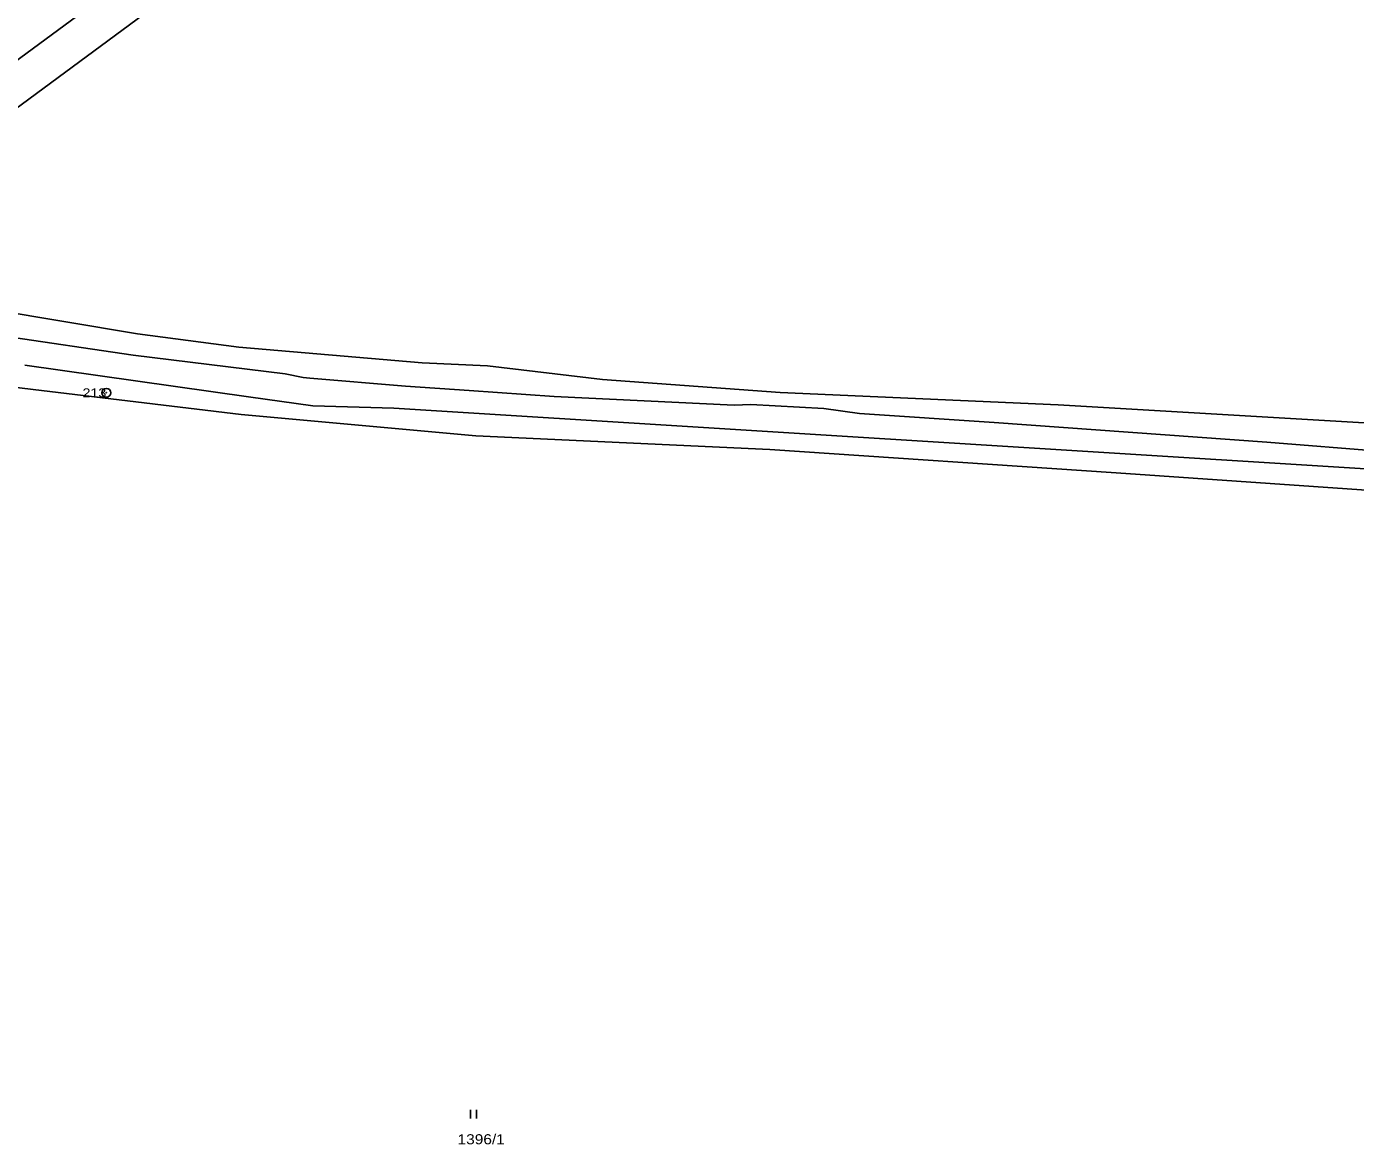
# Model space of a CAD drawing. Extents: x -872229 to -869198, y -1075981 to -1074329.
# Drawn here: x -870489.1 to -870264.6, y -1075125.3 to -1074936.4 of the extents above; entities that cross this region are included whole.
import ezdxf
from ezdxf.enums import TextEntityAlignment as Align

# ---------------------------------------------------------------- set-up
doc = ezdxf.new("R2010")
doc.units = 0
doc.header["$LTSCALE"] = 0.68
for name, color, linetype, lineweight in [('1', 7, 'Continuous', 25), ('3', 7, 'Continuous', 25), ('8', 7, 'Continuous', 25)]:
    doc.layers.add(name, color=color, linetype=linetype, lineweight=lineweight)
doc.layers.add('2', color=7, linetype='Continuous')

msp = doc.modelspace()

# ---------------------------------------------------------------- linework, layer by layer
at = {"layer": '1'}
for points in [[(-870352.08, -1074839.16), (-870370.51, -1074852.86), (-870398.03, -1074874.22), (-870412.45, -1074885.65), (-870420.69, -1074894.67), (-870447.23, -1074917.28), (-870451.03, -1074920.77), (-870491.11, -1074950.4), (-870524.35, -1074974.36)], [(-870388.3, -1074858.96), (-870401.56, -1074868.78), (-870415.98, -1074880.21), (-870424.22, -1074889.23), (-870450.76, -1074911.84), (-870454.56, -1074915.33), (-870494.64, -1074944.96)], [(-870115.36, -1074981.96), (-870117.37, -1074995.15), (-870140.21, -1074996.52), (-870172.56, -1075001.14), (-870203.84, -1075002.96), (-870227.79, -1075005.61), (-870254.49, -1075003.89), (-870314.81, -1075000.31), (-870361.75, -1074998.26), (-870391.78, -1074996.03), (-870411.2, -1074993.72), (-870422.25, -1074993.21), (-870453.27, -1074990.57), (-870470.34, -1074988.35), (-870494.98, -1074984.19), (-870516.43, -1074977.89), (-870524.35, -1074974.36)], [(-870610.36, -1075011.6), (-870588.87, -1075001.44), (-870569.21, -1074993.58), (-870546.64, -1074988.8), (-870536.79, -1074988.15), (-870527.6, -1074989.88), (-870515.91, -1074994.03), (-870492.69, -1074997.19), (-870452.83, -1075001.97), (-870413.18, -1075005.54), (-870363.54, -1075007.87), (-870304.97, -1075011.83), (-870245.64, -1075015.91), (-870217.62, -1075016.65), (-870207.57, -1075016.13)], [(-870240.2, -1075009.79), (-870279.52, -1075006.66), (-870325.61, -1075003.29), (-870348.35, -1075001.79), (-870354.38, -1075000.94), (-870366.75, -1075000.26), (-870369.54, -1075000.39), (-870399.94, -1074998.89), (-870414.32, -1074997.88), (-870425.07, -1074997.15), (-870441.24, -1074995.81), (-870442.36, -1074995.68), (-870445.44, -1074995.09), (-870471.11, -1074991.94), (-870493.23, -1074988.69)], [(-870489.43, -1074993.61), (-870451.62, -1074998.98), (-870440.72, -1075000.51), (-870427.04, -1075000.9), (-870260.16, -1075011.3)]]:
    msp.add_lwpolyline(points, dxfattribs=at)
at = {"layer": '3'}
for p, q in [((-870414.091, -1075120.97), (-870414.091, -1075119.47)), ((-870413.09, -1075120.97), (-870413.09, -1075119.47))]:
    msp.add_line(p, q, dxfattribs=at)
at = {"layer": '8'}
for radius in [0.75, 0.03]:
    msp.add_circle((-870475.64, -1074998.2898), radius, dxfattribs=at)

# ---------------------------------------------------------------- texts
at = {"layer": '2', "width": 1.15}
msp.add_text('1396/1', height=1.7, dxfattribs=at).set_placement((-870416.29, -1075125.32))
at = {"layer": '8', "width": 1.2}
msp.add_text('213', height=1.5, dxfattribs=at).set_placement((-870475.64, -1074999.04), align=Align.RIGHT)

doc.saveas('drawing.dxf')
